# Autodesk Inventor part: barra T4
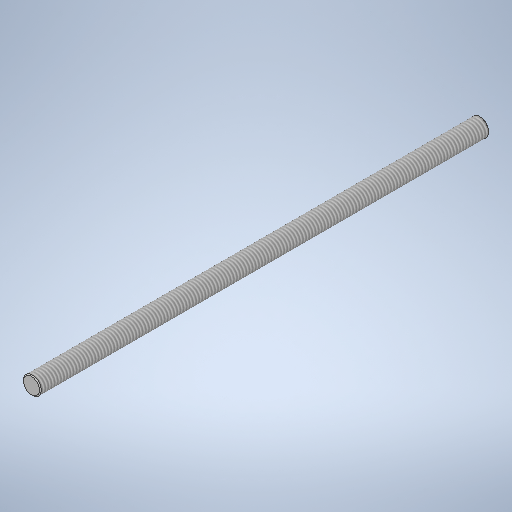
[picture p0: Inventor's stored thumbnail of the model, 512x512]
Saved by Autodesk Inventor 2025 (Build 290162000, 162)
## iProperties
Created: 2025-12
Part Number: barra T4
Material: Generico
Document SubType Name: Modeling
Designer: Ryzen5700u
Density: 1 g/cm^3
Appearance: Default
Author: Ryzen5700u
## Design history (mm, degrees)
sketch "Schizzo1"
  geometry: C1 r 2 at (0, 0); 1 further point
  constraints: 1 centre point, 1 coincident
  dimensions: "d0" = 4 diameter of C1
extrude "Estrusione1" new body sketch "Schizzo1" stored distance "d1" = 100; taper "d2" = 0 deg
feature "Filettatura1" dims "d3" = 100, "d4" = 0
chamfer "Smusso1" distance "d5" = 0.2; stored, may be unused: second distance "d6" = 2, angle "d7" = 45 deg
node "Solido1"
